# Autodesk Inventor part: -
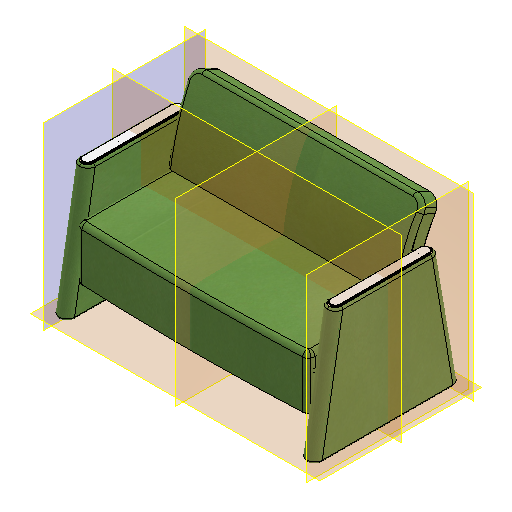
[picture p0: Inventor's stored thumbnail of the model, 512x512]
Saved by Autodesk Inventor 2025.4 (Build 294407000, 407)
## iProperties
Created: 2026-05
Part Number: -
Material: Generic
Description: BH 2-SEATER
Document SubType Name: Modeling
Designer: Brian.Thangei
Density: 1 g/cm^3
Appearance: Default
Project: SHORE
Sending System: SolidWorks 2026
Preprocessor: SwSTEP 2.0
Title: 1301.02 - SHORE BH 2-SEATER.STEP
Revision Number: ANY
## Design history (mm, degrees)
combine "NONE"
combine "NONE:1"
combine "NONE:2"
combine "NONE:3"
combine "NONE:4"
combine "NONE:5"
combine "NONE:6"
combine "NONE:7"
combine "NONE:8"
combine "NONE:9"
combine "NONE:10"
combine "NONE:11"
combine "NONE:12"
combine "Combine1"
combine "Combine2"
combine "Combine3"
combine "Combine4"
workplane "Work Plane1"
workplane "Work Plane2"
workplane "Work Plane3"
node "FOOT"
node "FOOT2"
node "FOOT3"
node "CORIAN"
node "FOOT4"
node "FOOT5"
node "CORIAN2"
node "ARM BASE"
node "FOOT6"
node "ARM BASE2"
node "ARM TOP"
node "ARM TOP2"
node "BASE"
node "BACK"
node "SEAT"
node "ARM"
node "ARM2"
other parameters: "d0" = 0, "d1" = 0
